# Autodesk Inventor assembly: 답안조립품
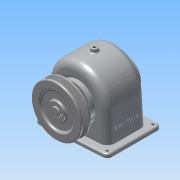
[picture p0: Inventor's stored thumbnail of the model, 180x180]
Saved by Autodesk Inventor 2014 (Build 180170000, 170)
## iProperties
Created: 2016-01
Part Number: 답안조립품
Document SubType Name: Assembly
Designer: User
Author: User
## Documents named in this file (16)
- C:\Documents and Settings\User\My Documents\Inventor\460106V1022\답안조립품.iam
- C:\Documents and Settings\User\바탕 화면\460106V1022\본체.ipt
- C:\Documents and Settings\User\My Documents\Inventor\460106V1022\축.ipt
- C:\Documents and Settings\User\My Documents\Inventor\460106V1022\뒤커버.ipt
- C:\Documents and Settings\User\My Documents\Inventor\460106V1022\베어링 6203.ipt
- C:\Documents and Settings\User\My Documents\Inventor\460106V1022\오일씰 28 40 8.ipt
- C:\Documents and Settings\User\My Documents\Inventor\460106V1022\부시1.ipt
- C:\Documents and Settings\User\My Documents\Inventor\460106V1022\부시2.ipt
- C:\Documents and Settings\User\My Documents\Inventor\460106V1022\스퍼기어.ipt
- C:\Documents and Settings\User\My Documents\Inventor\460106V1022\키 - 6 x 6 x 22.ipt
- C:\Documents and Settings\User\My Documents\Inventor\460106V1022\키 - 5 x 5 x 18.ipt
- C:\Documents and Settings\User\My Documents\Inventor\460106V1022\앞커버.ipt
- C:\Documents and Settings\User\My Documents\Inventor\460106V1022\V-벨트풀리.ipt
- C:\Documents and Settings\User\My Documents\Inventor\460106V1022\멈춤나사 - M4x10.ipt
- C:\Documents and Settings\User\My Documents\Inventor\460106V1022\볼트 M3 x 10.ipt
- C:\Documents and Settings\User\My Documents\Inventor\460106V1022\볼트 M3 x 8.ipt
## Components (9 placed, 3 different names)
1. V-벨트풀리:1
2. ISO 4762 M3 x 8:1
3. ISO 4762 M3 x 10:1
4. ISO 4762 M3 x 8:2
5. ISO 4762 M3 x 10:2
6. ISO 4762 M3 x 8:3
7. ISO 4762 M3 x 10:3
8. ISO 4762 M3 x 8:4
9. ISO 4762 M3 x 10:4
